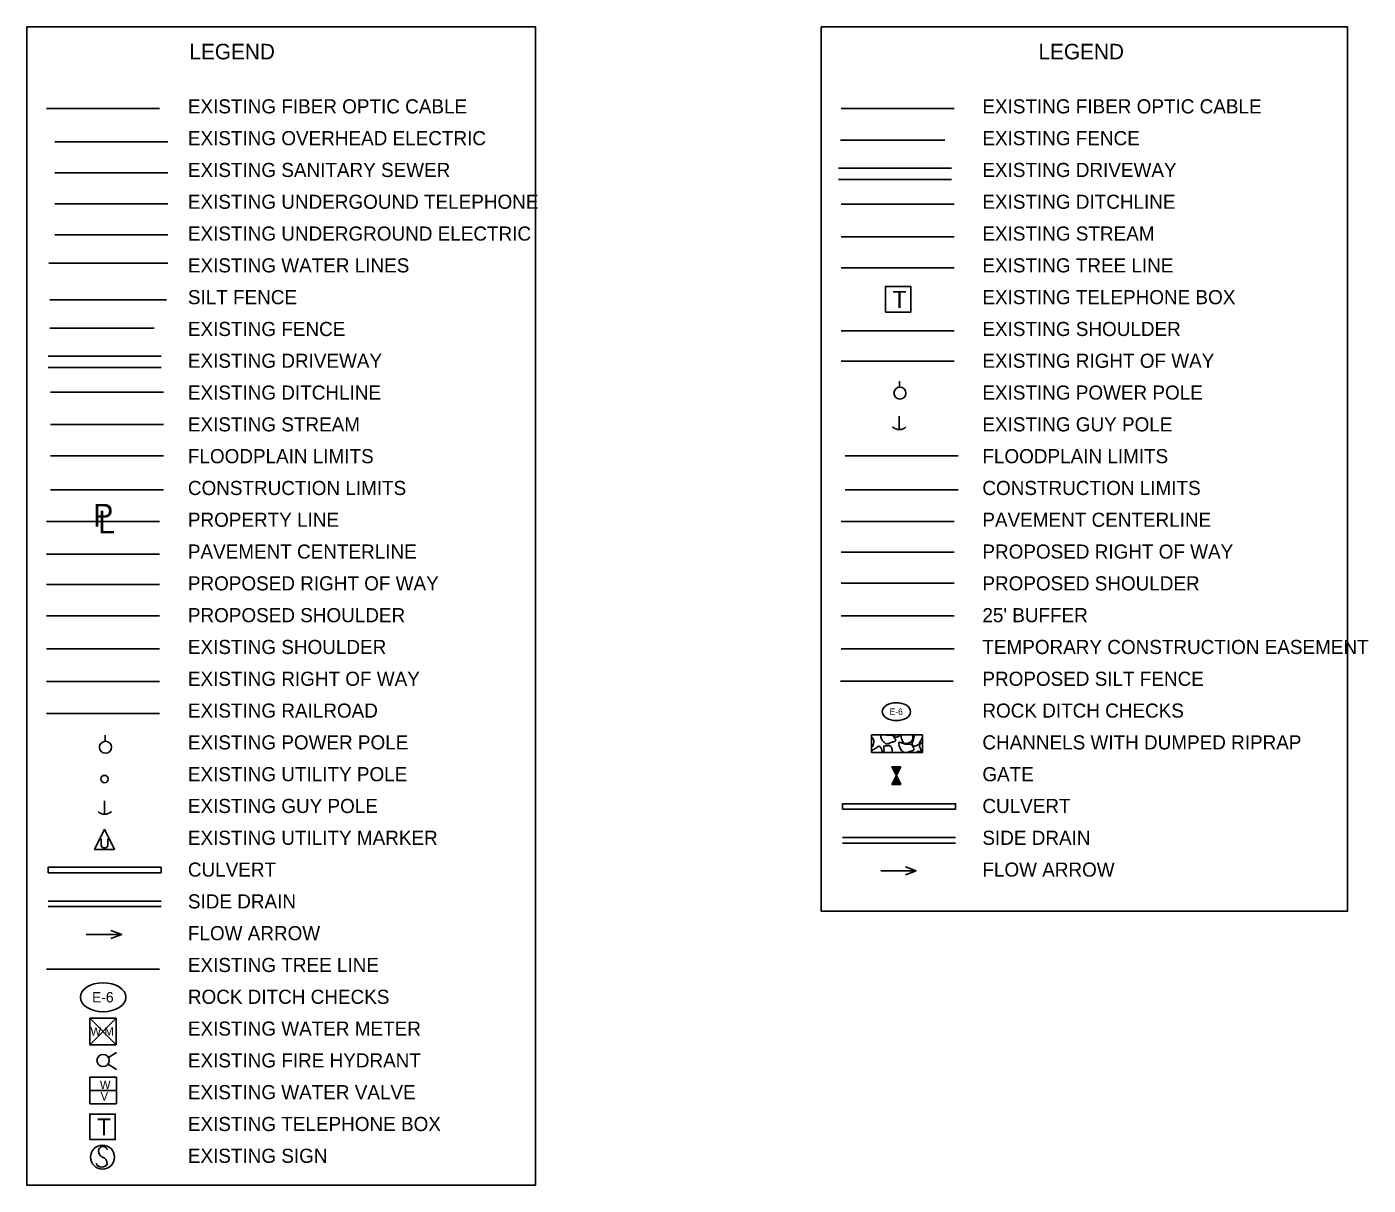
# Model space of a CAD drawing. Extents: x 9709 to 12772, y 9986 to 11806.
# Drawn here: x 12012 to 12772, y 10285 to 10940 of the extents above; entities that cross this region are included whole.
import ezdxf

# ---------------------------------------------------------------- set-up
doc = ezdxf.new("R2010")
doc.units = 0
for name, color, linetype in [('Legend', 7, 'Continuous'), ('R_Proposed Const Limits', 7, 'Continuous'), ('S_DITCHLINE', 7, 'Continuous'), ('S_FIBER_OPTIC_CABLE', 7, 'Continuous'), ('S_SHOULDER', 7, 'Continuous'), ('S_STREAM', 7, 'Continuous')]:
    doc.layers.add(name, color=color, linetype=linetype)

msp = doc.modelspace()

# ---------------------------------------------------------------- linework, layer by layer
at = {"layer": 'Legend'}
for p, q in [((12473.65, 10894), (12537.65, 10894)), ((12028.35, 10875.21), (12092.35, 10875.21)), ((12473.23, 10876.01), (12525.72, 10876.01)), ((12532.31, 10876.01), (12525.72, 10876.01)), ((12028.35, 10857.61), (12092.35, 10857.61)), ((12472.22, 10860.18), (12536.22, 10860.18)), ((12472.22, 10853.78), (12536.22, 10853.78)), ((12028.35, 10840.01), (12092.35, 10840.01)), ((12473.65, 10839.8), (12537.65, 10839.8)), ((12028.35, 10822.41), (12092.35, 10822.41)), ((12473.65, 10821.44), (12537.65, 10821.44)), ((12024.9, 10806.41), (12092.35, 10806.41)), ((12473.65, 10803.72), (12537.65, 10803.72)), ((12025.54, 10785.61), (12091.57, 10785.61)), ((12025.54, 10769.61), (12078.03, 10769.61)), ((12084.61, 10769.61), (12078.03, 10769.61)), ((12473.65, 10768.09), (12537.65, 10768.09)), ((12024.52, 10753.78), (12088.52, 10753.78)), ((12473.65, 10751.07), (12537.65, 10751.07)), ((12024.52, 10747.38), (12088.52, 10747.38)), ((12506.79, 10736.33), (12506.79, 10739.7)), ((12506.46, 10719.8), (12506.46, 10712.23)), ((12025.95, 10697.32), (12089.95, 10697.32)), ((12475.89, 10697.32), (12539.89, 10697.32)), ((12475.89, 10678.12), (12539.89, 10678.12)), ((12023.71, 10660.25), (12087.71, 10660.25)), ((12473.65, 10660.25), (12537.65, 10660.25)), ((12473.65, 10642.95), (12537.65, 10642.95)), ((12023.71, 10641.79), (12087.71, 10641.79)), ((12023.71, 10624.49), (12087.71, 10624.49)), ((12473.65, 10625.26), (12537.65, 10625.26)), ((12023.71, 10606.8), (12087.71, 10606.8)), ((12473.65, 10606.8), (12537.65, 10606.8)), ((12473.65, 10588.06), (12537.65, 10588.06)), ((12023.71, 10569.71), (12087.71, 10569.71)), ((12473.23, 10569.85), (12537.1, 10569.85)), ((12023.71, 10551.53), (12087.71, 10551.53)), ((12056.85, 10535.84), (12056.85, 10539.22)), ((12507.43, 10521.34), (12502.5, 10521.34)), ((12507.38, 10521.24), (12502.55, 10521.24)), ((12507.33, 10521.14), (12502.6, 10521.14)), ((12507.28, 10521.04), (12502.65, 10521.04)), ((12507.23, 10520.94), (12502.7, 10520.94)), ((12507.18, 10520.84), (12502.75, 10520.84)), ((12507.13, 10520.74), (12502.8, 10520.74)), ((12507.08, 10520.64), (12502.85, 10520.64)), ((12507.03, 10520.54), (12502.9, 10520.54)), ((12506.98, 10520.44), (12502.95, 10520.44)), ((12506.93, 10520.34), (12503, 10520.34)), ((12506.88, 10520.24), (12503.05, 10520.24)), ((12506.83, 10520.14), (12503.1, 10520.14)), ((12506.78, 10520.04), (12503.15, 10520.04)), ((12506.73, 10519.94), (12503.2, 10519.94)), ((12506.68, 10519.84), (12503.25, 10519.84)), ((12506.63, 10519.74), (12503.3, 10519.74)), ((12506.58, 10519.64), (12503.35, 10519.64)), ((12506.53, 10519.54), (12503.4, 10519.54)), ((12506.48, 10519.44), (12503.45, 10519.44)), ((12506.46, 10513.43), (12503.47, 10513.43)), ((12506.43, 10519.34), (12503.5, 10519.34)), ((12506.41, 10513.53), (12503.52, 10513.53)), ((12506.38, 10519.24), (12503.55, 10519.24)), ((12506.36, 10513.63), (12503.57, 10513.63)), ((12506.33, 10519.14), (12503.6, 10519.14)), ((12506.31, 10513.73), (12503.62, 10513.73)), ((12506.28, 10519.04), (12503.65, 10519.04)), ((12506.26, 10513.83), (12503.67, 10513.83)), ((12506.23, 10518.94), (12503.7, 10518.94)), ((12506.21, 10513.93), (12503.72, 10513.93)), ((12506.18, 10518.84), (12503.75, 10518.84)), ((12506.16, 10514.03), (12503.77, 10514.03)), ((12506.13, 10518.74), (12503.8, 10518.74)), ((12506.11, 10514.13), (12503.82, 10514.13)), ((12506.08, 10518.64), (12503.85, 10518.64)), ((12506.06, 10514.23), (12503.87, 10514.23)), ((12506.03, 10518.54), (12503.9, 10518.54)), ((12506.01, 10514.33), (12503.92, 10514.33)), ((12505.98, 10518.44), (12503.95, 10518.44)), ((12505.96, 10514.43), (12503.97, 10514.43)), ((12505.93, 10518.34), (12504, 10518.34)), ((12505.91, 10514.53), (12504.02, 10514.53)), ((12505.88, 10518.24), (12504.05, 10518.24)), ((12505.86, 10514.63), (12504.07, 10514.63)), ((12505.83, 10518.14), (12504.1, 10518.14)), ((12505.81, 10514.73), (12504.12, 10514.73)), ((12505.78, 10518.04), (12504.15, 10518.04)), ((12505.76, 10514.83), (12504.17, 10514.83)), ((12505.73, 10517.94), (12504.2, 10517.94)), ((12505.71, 10514.93), (12504.22, 10514.93)), ((12505.68, 10517.84), (12504.25, 10517.84)), ((12505.66, 10515.03), (12504.27, 10515.03)), ((12505.63, 10517.74), (12504.3, 10517.74)), ((12505.61, 10515.13), (12504.32, 10515.13)), ((12505.58, 10517.64), (12504.35, 10517.64)), ((12505.56, 10515.23), (12504.37, 10515.23)), ((12505.53, 10517.54), (12504.4, 10517.54)), ((12505.51, 10515.33), (12504.42, 10515.33)), ((12505.48, 10517.44), (12504.45, 10517.44)), ((12505.46, 10515.43), (12504.47, 10515.43)), ((12505.43, 10517.34), (12504.5, 10517.34)), ((12505.41, 10515.53), (12504.52, 10515.53)), ((12505.38, 10517.24), (12504.55, 10517.24)), ((12505.36, 10515.63), (12504.57, 10515.63)), ((12505.33, 10517.14), (12504.6, 10517.14)), ((12505.31, 10515.73), (12504.62, 10515.73)), ((12505.28, 10517.04), (12504.65, 10517.04)), ((12505.26, 10515.83), (12504.67, 10515.83)), ((12505.23, 10516.94), (12504.7, 10516.94)), ((12505.21, 10515.93), (12504.72, 10515.93)), ((12505.18, 10516.84), (12504.75, 10516.84)), ((12505.16, 10516.03), (12504.77, 10516.03)), ((12505.13, 10516.74), (12504.8, 10516.74)), ((12505.11, 10516.13), (12504.82, 10516.13)), ((12505.08, 10516.64), (12504.85, 10516.64)), ((12505.06, 10516.23), (12504.87, 10516.23)), ((12505.03, 10516.54), (12504.9, 10516.54)), ((12505.01, 10516.33), (12504.92, 10516.33)), ((12504.98, 10516.44), (12504.95, 10516.44)), ((12507.46, 10511.43), (12502.47, 10511.43)), ((12507.41, 10511.53), (12502.52, 10511.53)), ((12507.36, 10511.63), (12502.57, 10511.63)), ((12507.31, 10511.73), (12502.62, 10511.73)), ((12507.26, 10511.83), (12502.67, 10511.83)), ((12507.21, 10511.93), (12502.72, 10511.93)), ((12507.16, 10512.03), (12502.77, 10512.03)), ((12507.11, 10512.13), (12502.82, 10512.13)), ((12507.06, 10512.23), (12502.87, 10512.23)), ((12507.01, 10512.33), (12502.92, 10512.33)), ((12506.96, 10512.43), (12502.97, 10512.43)), ((12506.91, 10512.53), (12503.02, 10512.53)), ((12506.86, 10512.63), (12503.07, 10512.63)), ((12506.81, 10512.73), (12503.12, 10512.73)), ((12506.76, 10512.83), (12503.17, 10512.83)), ((12506.71, 10512.93), (12503.22, 10512.93)), ((12506.66, 10513.03), (12503.27, 10513.03)), ((12506.61, 10513.13), (12503.32, 10513.13)), ((12506.56, 10513.23), (12503.37, 10513.23)), ((12506.51, 10513.33), (12503.42, 10513.33)), ((12056.52, 10502.06), (12056.52, 10494.5)), ((12474.46, 10497.42), (12538.46, 10497.42)), ((12056.52, 10485.99), (12050.88, 10474.65)), ((12056.52, 10485.99), (12062.1, 10474.65)), ((12054.6, 10476.63), (12054.6, 10480.54)), ((12055.59, 10475.58), (12054.6, 10476.63)), ((12057.51, 10475.58), (12055.59, 10475.58)), ((12058.38, 10476.63), (12057.51, 10475.58)), ((12058.38, 10480.54), (12058.38, 10476.63)), ((12474.46, 10481.32), (12538.46, 10481.32)), ((12474.46, 10478.25), (12538.46, 10478.25)), ((12050.88, 10474.65), (12062.1, 10474.65)), ((12024.52, 10461.42), (12088.52, 10461.42)), ((12496.08, 10462.51), (12516.19, 10462.51)), ((12516.19, 10462.51), (12510.03, 10464.75)), ((12516.19, 10462.51), (12510.03, 10460.27)), ((12024.52, 10445.32), (12088.52, 10445.32)), ((12024.52, 10442.25), (12088.52, 10442.25)), ((12046.14, 10426.51), (12066.25, 10426.51)), ((12066.25, 10426.51), (12060.1, 10428.75)), ((12066.25, 10426.51), (12060.1, 10424.27)), ((12023.71, 10406.85), (12087.71, 10406.85)), ((12048.23, 10379.18), (12063.17, 10379.18)), ((12048.23, 10379.18), (12048.23, 10363.99)), ((12048.23, 10379.18), (12063.17, 10363.99)), ((12063.17, 10379.18), (12048.23, 10363.99)), ((12063.17, 10379.18), (12063.17, 10363.99)), ((12048.23, 10363.99), (12063.17, 10363.99)), ((12058.75, 10356.84), (12063.27, 10359.61)), ((12058.55, 10353.14), (12063.2, 10350.06)), ((12048.17, 10345.65), (12063.23, 10345.65)), ((12048.17, 10330.59), (12048.17, 10345.65)), ((12063.23, 10345.65), (12063.23, 10330.59)), ((12048.17, 10338.15), (12063.23, 10338.15)), ((12063.23, 10330.59), (12048.17, 10330.59))]:
    msp.add_line(p, q, dxfattribs=at)
for points in [[(12012.49, 10940.21), (12300.52, 10940.21), (12300.52, 10284.58), (12012.49, 10284.58)], [(12462.43, 10940.21), (12760.45, 10940.21), (12760.45, 10439.58), (12462.43, 10439.58)], [(12498.71, 10778.76), (12498.71, 10793.16), (12513.11, 10793.16), (12513.11, 10778.76)], [(12507.46, 10521.42), (12504.96, 10516.42), (12502.46, 10521.42)], [(12507.46, 10511.42), (12504.96, 10516.42), (12502.46, 10511.42)], [(12048.14, 10310.41), (12048.14, 10324.81), (12062.54, 10324.81), (12062.54, 10310.41)]]:
    msp.add_lwpolyline(points, close=True, dxfattribs=at)
for points in [[(12519.79, 10539.47), (12490.86, 10539.47), (12490.86, 10529.48)], [(12519.79, 10539.47), (12519.79, 10529.48), (12490.86, 10529.48)], [(12519.79, 10539.47), (12490.86, 10539.47), (12490.86, 10529.48)], [(12490.86, 10529.48), (12519.79, 10529.48), (12519.79, 10539.47)], [(12474.46, 10497.42), (12474.46, 10500.49), (12538.46, 10500.49), (12538.46, 10497.42)], [(12024.52, 10461.42), (12024.52, 10464.49), (12088.52, 10464.49), (12088.52, 10461.42)]]:
    msp.add_lwpolyline(points, dxfattribs=at)
for centre, radius in [((12506.98, 10732.9), 3.4), ((12057.05, 10532.42), 3.4), ((12056.52, 10514.46), 2.09), ((12055.7, 10355.15), 3.48), ((12055.37, 10300.45), 6.78)]:
    msp.add_circle(centre, radius, dxfattribs=at)
for centre, radius, start, end in [((12506.56, 10717.72), 5.46, 226.39718, 313.60282), ((12056.62, 10499.98), 5.46, 226.39718, 313.60282), ((12057.24, 10304.06), 4.09, 167.11961, 241.98129), ((12055.58, 10303.9), 2.58, 16.52583, 156.89569), ((12054.96, 10298.21), 3.47, 204.64102, 335.35898), ((12054.25, 10296.8), 3.8, 358.65289, 73.70634)]:
    msp.add_arc(centre, radius, start, end, dxfattribs=at)
for centre, major_axis, ratio in [((12504.96, 10552.59), (7.98, 0), 0.636915), ((12055.71, 10390.94), (12.88, 0), 0.638788)]:
    msp.add_ellipse(centre, major_axis=major_axis, ratio=ratio, dxfattribs=at)
for points, degree in [([(12491.13, 10532.42), (12491.21, 10532.57), (12491.28, 10532.71), (12491.81, 10533.91), (12492.23, 10534.93), (12491.99, 10537.02), (12491.63, 10537.68), (12491.13, 10538.1)], 3), ([(12495.94, 10539.43), (12495.99, 10538.88), (12496.17, 10538.24), (12496.63, 10537.01), (12496.96, 10536.26), (12498.17, 10534.95), (12499.24, 10534.24), (12500.74, 10534.65), (12501.27, 10534.83), (12502.58, 10535.28), (12503.34, 10535.56), (12504.38, 10535.97), (12504.62, 10536.41), (12504.36, 10537.04), (12504.06, 10537.31), (12503.69, 10538), (12503.73, 10538.61), (12503.06, 10538.99), (12502.77, 10539.16), (12502.47, 10539.32)], 3), ([(12502.48, 10539.3), (12501.75, 10539.27), (12501.02, 10539.24), (12499.85, 10539.2), (12499.43, 10539.31), (12499.01, 10539.44)], 3), ([(12503.57, 10539.47), (12503.64, 10539.14), (12503.78, 10538.83), (12504.3, 10538.05), (12505.57, 10538.14), (12506.64, 10538.89), (12506.93, 10539.17), (12507.18, 10539.48)], 3), ([(12508.18, 10539.49), (12507.22, 10538.75), (12508.03, 10537.12), (12508.87, 10534.46), (12510.48, 10534.4), (12512.59, 10535.16), (12513.42, 10535.62), (12514.19, 10536.85), (12514.32, 10537.47), (12514.35, 10538.6), (12514.31, 10539.06), (12514.22, 10539.51)], 3), ([(12515.29, 10539.52), (12515.11, 10538.86), (12514.93, 10538.21), (12514.54, 10536.77), (12514.17, 10536.04), (12513.83, 10534.64), (12514.08, 10533.9), (12514.73, 10532.92), (12516, 10533.01), (12517.49, 10534.06), (12517.95, 10534.77), (12518.68, 10535.95), (12518.92, 10536.4), (12519.27, 10537.17), (12519.4, 10537.48), (12519.52, 10537.8)], 3), ([(12493.26, 10531.98), (12492.55, 10531.51), (12491.84, 10531.04), (12491.13, 10530.57)], 2), ([(12496.97, 10529.44), (12496.94, 10530.13), (12496.81, 10530.76), (12496.26, 10532.24), (12495.27, 10533.38), (12494.15, 10532.61), (12493.71, 10532.3), (12493.27, 10532)], 3), ([(12498.02, 10530.71), (12497.91, 10530.29), (12497.79, 10529.87), (12497.67, 10529.44)], 2), ([(12502.41, 10529.47), (12502.53, 10529.97), (12502.58, 10530.51), (12502.41, 10531.95), (12502, 10532.65), (12501.07, 10533.35), (12500.51, 10533.42), (12499.06, 10533.21), (12497.62, 10533.37), (12497.81, 10531.97), (12497.89, 10531.34), (12497.98, 10530.71)], 3), ([(12512.91, 10534.17), (12512.18, 10534.14), (12511.44, 10534.12), (12509.83, 10534.06), (12509, 10534.52), (12507.71, 10534.9), (12507.32, 10535.25), (12506.01, 10535.44), (12506.42, 10533.56), (12507.06, 10531.88), (12507.39, 10531.13), (12508.32, 10530.12), (12508.83, 10529.72), (12509.38, 10529.5)], 3), ([(12511.08, 10529.5), (12511.47, 10529.62), (12511.85, 10529.76), (12513.01, 10530.15), (12513.77, 10530.43), (12514.81, 10530.84), (12515.05, 10531.28), (12514.78, 10531.92), (12514.49, 10532.18), (12514.12, 10532.87), (12514.16, 10533.48), (12513.49, 10533.86), (12513.19, 10534.03), (12512.9, 10534.2)], 3), ([(12518.9, 10529.54), (12518.8, 10529.58), (12518.69, 10529.61), (12518.14, 10529.78), (12517.75, 10530.13), (12516.94, 10530.24), (12516.8, 10529.95), (12516.79, 10529.53)], 3), ([(12519.52, 10534.97), (12519.24, 10534.78), (12518.96, 10534.6), (12517.61, 10533.7), (12518.45, 10532.02), (12519.02, 10530.21), (12519.24, 10529.95), (12519.52, 10529.77)], 3)]:
    msp.add_open_spline(points, degree=degree, dxfattribs=at)
at = {"layer": 'R_Proposed Const Limits'}
msp.add_line((12025.95, 10678.12), (12089.95, 10678.12), dxfattribs=at)
at = {"layer": 'S_DITCHLINE'}
msp.add_line((12025.95, 10733.4), (12089.95, 10733.4), dxfattribs=at)
at = {"layer": 'S_FIBER_OPTIC_CABLE'}
msp.add_line((12023.71, 10894), (12087.71, 10894), dxfattribs=at)
at = {"layer": 'S_SHOULDER'}
msp.add_line((12023.71, 10588.06), (12087.71, 10588.06), dxfattribs=at)
at = {"layer": 'S_STREAM'}
msp.add_line((12025.95, 10715.04), (12089.95, 10715.04), dxfattribs=at)

# ---------------------------------------------------------------- texts
at = {"layer": 'Legend'}
for s, height, p in [('LEGEND', 8.8, (12104.58, 10921.81)), ('LEGEND', 8.8, (12585.44, 10921.81)), ('EXISTING FIBER OPTIC CABLE', 8, (12103.71, 10891.21)), ('EXISTING FIBER OPTIC CABLE', 8, (12553.65, 10891.21)), ('EXISTING OVERHEAD ELECTRIC', 8, (12103.71, 10873.21)), ('EXISTING FENCE', 8, (12553.65, 10873.21)), ('EXISTING SANITARY SEWER', 8, (12103.71, 10855.21)), ('EXISTING DRIVEWAY', 8, (12553.65, 10855.21)), ('EXISTING UNDERGOUND TELEPHONE', 8, (12103.71, 10837.21)), ('EXISTING DITCHLINE', 8, (12553.65, 10837.21)), ('EXISTING UNDERGROUND ELECTRIC', 8, (12103.71, 10819.21)), ('EXISTING STREAM', 8, (12553.65, 10819.21)), ('EXISTING WATER LINES', 8, (12103.71, 10801.21)), ('EXISTING TREE LINE', 8, (12553.65, 10801.21)), ('SILT FENCE', 8, (12103.71, 10783.21)), ('T', 9.6, (12502.81, 10781.16)), ('EXISTING TELEPHONE BOX', 8, (12553.65, 10783.21)), ('EXISTING FENCE', 8, (12103.71, 10765.21)), ('EXISTING SHOULDER', 8, (12553.65, 10765.21)), ('EXISTING DRIVEWAY', 8, (12103.71, 10747.21)), ('EXISTING RIGHT OF WAY', 8, (12553.65, 10747.21)), ('EXISTING DITCHLINE', 8, (12103.71, 10729.21)), ('EXISTING POWER POLE', 8, (12553.65, 10729.21)), ('EXISTING STREAM', 8, (12103.71, 10711.21)), ('EXISTING GUY POLE', 8, (12553.65, 10711.21)), ('FLOODPLAIN LIMITS', 8, (12103.71, 10693.21)), ('FLOODPLAIN LIMITS', 8, (12553.65, 10693.21)), ('CONSTRUCTION LIMITS', 8, (12103.71, 10675.21)), ('CONSTRUCTION LIMITS', 8, (12553.65, 10675.21)), ('P', 12.8, (12050.08, 10657.36)), ('L', 12.8, (12052.89, 10653.47)), ('PROPERTY LINE', 8, (12103.71, 10657.21)), ('PAVEMENT CENTERLINE', 8, (12553.65, 10657.21)), ('PAVEMENT CENTERLINE', 8, (12103.71, 10639.21)), ('PROPOSED RIGHT OF WAY', 8, (12553.65, 10639.21)), ('PROPOSED RIGHT OF WAY', 8, (12103.71, 10621.21)), ('PROPOSED SHOULDER', 8, (12553.65, 10621.21)), ('PROPOSED SHOULDER', 8, (12103.71, 10603.21)), ("25' BUFFER", 8, (12553.65, 10603.21)), ('EXISTING SHOULDER', 8, (12103.71, 10585.21)), ('TEMPORARY CONSTRUCTION EASEMENT', 8, (12553.65, 10585.21)), ('EXISTING RIGHT OF WAY', 8, (12103.71, 10567.21)), ('PROPOSED SILT FENCE', 8, (12553.65, 10567.21)), ('EXISTING RAILROAD', 8, (12103.71, 10549.21)), ('E-6', 3.628, (12501.07, 10550.77)), ('ROCK DITCH CHECKS', 8, (12553.65, 10549.21)), ('EXISTING POWER POLE', 8, (12103.71, 10531.21)), ('CHANNELS WITH DUMPED RIPRAP', 8, (12553.65, 10531.21)), ('EXISTING UTILITY POLE', 8, (12103.71, 10513.21)), ('GATE', 8, (12553.65, 10513.21)), ('EXISTING GUY POLE', 8, (12103.71, 10495.21)), ('CULVERT', 8, (12553.65, 10495.21)), ('EXISTING UTILITY MARKER', 8, (12103.71, 10477.21)), ('SIDE DRAIN', 8, (12553.65, 10477.21)), ('CULVERT', 8, (12103.71, 10459.21)), ('FLOW ARROW', 8, (12553.65, 10459.21)), ('SIDE DRAIN', 8, (12103.71, 10441.21)), ('FLOW ARROW', 8, (12103.71, 10423.21)), ('EXISTING TREE LINE', 8, (12103.71, 10405.21)), ('E-6', 5.878, (12049.42, 10388)), ('ROCK DITCH CHECKS', 8, (12103.71, 10387.21)), ('EXISTING WATER METER', 8, (12103.71, 10369.21)), ('W M', 4.8, (12048.56, 10369.2)), ('EXISTING FIRE HYDRANT', 8, (12103.71, 10351.21)), ('W', 4.8, (12053.85, 10339)), ('EXISTING WATER VALVE', 8, (12103.71, 10333.21)), ('V', 4.8, (12054.23, 10332.5)), ('T', 9.6, (12052.24, 10312.81)), ('EXISTING TELEPHONE BOX', 8, (12103.71, 10315.21)), ('EXISTING SIGN', 8, (12103.71, 10297.21))]:
    msp.add_text(s, height=height, dxfattribs=at).set_placement(p)

doc.saveas('drawing.dxf')
